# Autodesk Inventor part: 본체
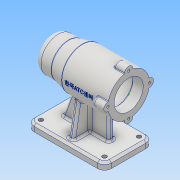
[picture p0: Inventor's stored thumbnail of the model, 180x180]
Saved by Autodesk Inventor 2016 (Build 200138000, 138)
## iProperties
Created: 2019-07
Part Number: 본체
Material: 알루미늄 6061
Document SubType Name: Modeling
Designer: 3sil_cad0123
Density: 2.7 g/cm^3
Appearance: 알루미늄 - 평지
Mass: 644.247 g
Surface Area: 655.732 cm^2
Volume: 238.61 cm^3
Author: 3sil_cad0123
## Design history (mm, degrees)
sketch "스케치1"
  geometry: 1 further point
sketch "스케치2"
  geometry: L1 (0, 0)-(0, 30); L2 (0, 30)-(-67, 30); L3 (-67, 30)-(-87, 25); L4 (-87, 25)-(-102, 25); L5 (-112, 15)-(-112, 0); L6 (-112, 0)-(0, 0); A1 r 10 centre (-102, 15) between (-102, 25) and (-112, 15); 1 further point
  constraints: 12 end point, 3 perpendicular, 2 point on circle, 2 point on line, 2 tangent, 1 centre point, 1 parallel, 1 vertical
  dimensions: "d0" = 112 distance between parallel lines of L1 L5; "d1" = 45 distance from line of L2.end L5; "d2" = 25 distance of L3.end point (-112, 25); "d3" = 60 diameter of L2 L6; "d4" = 50 diameter of L4 L6; "d5" = 10 radius of A1
revolve "회전1" sketch "스케치2" stored, may be unused: angle "d6" = 90 deg
sketch "스케치3"
  geometry: L1 (0, 0)-(-15, 0); L2 (-15, 0)-(-15, 21); L3 (-15, 21)-(0, 21); L4 (0, 21)-(0, 0); L5 (-15, 0)-(-69, 0); L6 (-69, 0)-(-69, 21); L7 (-66, 24)-(-18, 24); L8 (-15, 21)-(-15, 0); L9 (-69, 0)-(-81, 0); L10 (-81, 0)-(-81, 20.7); L11 (-80.7, 21)-(-69, 21); L12 (-69, 21)-(-69, 0); L13 (-81, 0)-(-99, 0); L14 (-99, 0)-(-99, 17.2); L15 (-98.7, 17.5)-(-81, 17.5); L16 (-81, 17.5)-(-81, 0); L17 (-99, 0)-(-103, 0); L18 (-103, 0)-(-103, 15.7); L19 (-102.7, 16)-(-99, 16); L20 (-99, 16)-(-99, 0); L21 (-103, 0)-(-106, 0); L22 (-106, 0)-(-106, 10.5); L23 (-106, 10.5)-(-103, 10.5); L24 (-103, 10.5)-(-103, 0); A1 r 0.3 centre (-80.7, 20.7) between (-80.7, 21) and (-81, 20.7); A2 r 0.3 centre (-98.7, 17.2) between (-98.7, 17.5) and (-99, 17.2); A3 r 0.3 centre (-102.7, 15.7) between (-102.7, 16) and (-103, 15.7); A4 r 3 centre (-66, 21) between (-66, 24) and (-69, 21); A5 r 3 centre (-18, 21) between (-15, 21) and (-18, 24); 5 further points
  constraints: 48 end point, 12 parallel, 10 point on circle, 10 point on line, 10 tangent, 6 horizontal, 6 perpendicular, 5 centre point, 3 equal radius
  dimensions: "d9" = 21 distance between parallel lines of L9 L11; "d10" = 17.5 distance between parallel lines of L13 L15; "d11" = 16 distance between parallel lines of L17 L19; "d12" = 10.5 distance between parallel lines of L21 L23; "d13" = 15 distance of L2.end L3.end; "d14" = 24 distance between parallel lines of L5 L7; "d15" = 21 distance between parallel lines of L1 L3; "d16" = 54 distance of point (-69, 24) point (-15, 24); "d17" = 12 distance of point (-81, 21) L11.end; "d18" = 18 distance of point (-99, 17.5) L15.end; "d19" = 4 distance of point (-103, 16) L19.end; "d20" = 3 distance of L22.end L23.end; "d21" = 0.3 radius of A1; "d22" = 3 radius of A4
revolve "회전2" sketch "스케치3" stored, may be unused: angle "d23" = 90 deg
sketch "스케치4"
  geometry: C1 r 21 at (0, 0) reference; C2 r 6 at (0, 30); C3 r 6 at (-30, 0); C4 r 6 at (0, -30); C5 r 6 at (30, 0); 1 further point
  constraints: 4 centre point, 1 vertical alignment, 10 other
  dimensions: "d26" = 360 deg dimension on C1.centre C2.centre (derived)
extrude "돌출1" join sketch "스케치4" distance "d28" = 16; taper "d29" = 0 deg
sketch "스케치5"
  geometry: A1 r 6 centre (30, 30) between (35.97, 29.4) and (24.03, 29.4) reference; A2 r 6 centre (0, 0) between (0.6, 5.97) and (0.6, -5.97) reference; A3 r 6 centre (30, -30) between (24.03, -29.4) and (35.97, -29.4) reference; A4 r 6 centre (60, 0) between (59.4, -5.97) and (59.4, 5.97) reference
hole "구멍1" sketch "스케치5" at (60, 0), (30, -30), (0, 0), (30, 30) diameter "d30" = 3.242; stored, may be unused: countersink angle "d34" = 90 deg, drill point angle "d36" = 118 deg; dims "d31" = 8, "d32" = 4, "d33" = 2, "d35" = 11
fillet "모깎기1" dims "d37" = 3
fillet "모깎기2" dims "d38" = 1
node "작업 평면1"
sketch "스케치6"
  geometry: L1 (0, -35)-(112, -35); L2 (112, -35)-(112, 35); L3 (112, 35)-(0, 35); L4 (0, 35)-(0, -35); 2 further points
  constraints: 8 end point, 2 parallel, 1 coincident, 1 horizontal, 1 midpoint, 1 perpendicular
  dimensions: "d40" = 112 distance of L2.end L3.end; "d41" = 70 distance of L1.end L2.end
extrude "돌출2" join sketch "스케치6" distance "d42" = 10; taper "d43" = 0 deg
fillet "모깎기3" dims "d44" = 10
sketch "스케치7"
  geometry: A1 r 10 centre (102, -25) between (102, -35) and (112, -25) reference; A2 r 10 centre (102, 25) between (112, 25) and (102, 35) reference; A3 r 10 centre (10, 25) between (10, 35) and (0, 25) reference; A4 r 10 centre (10, -25) between (0, -25) and (10, -35) reference; 1 further point
hole "구멍2" sketch "스케치7" at (10, 25), (10, -25), (102, -25), (102, 25) diameter "d45" = 6; stored, may be unused: countersink angle "d49" = 90 deg, drill point angle "d51" = 118 deg; dims "d46" = 8, "d47" = 4, "d48" = 2, "d50" = 11
node "작업 평면2"
sketch "스케치8"
  geometry: L1 (0, 6.771)-(0, 29.226) reference; 2 further points
  constraints: 1 horizontal alignment, 1 other
  dimensions: "d53" = 42 distance from line of L1 point (-42, 0)
feature "엠보싱1" sketch "스케치8" dims "d0" = 112, "d1" = 45, "d2" = 25, "d3" = 60, "d4" = 50, "d5" = 10, "d54" = 0.5, "d55" = 0
node "작업 평면3"
sketch "스케치10"
  geometry: L1 (-35, -70)-(-25, -70) reference; L2 (-28, -70)-(-19.207, -20.133); L3 (19.206, -20.126)-(28, -70); L4 (25, -70)-(35, -70) reference; L5 (-28, -70)-(28, -70); L6 (-35, -80)-(-35, -70) reference; L7 (35, -70)-(35, -80) reference; L8 (-19.207, -20.133)-(-5.193, -26.929); L9 (-5.193, -26.929)-(5.853, -26.929); L10 (5.853, -26.929)-(19.206, -20.126); 1 further point
  constraints: 12 end point, 2 point on line, 1 collinear, 1 horizontal
  dimensions: "d61" = 7 distance from line of L2.start L6; "d62" = 7 distance from line of L3.end L7; "d63" = 100 deg angle of L3 L4; "d64" = 100 deg angle of L1 L2
extrude "돌출3" join sketch "스케치10" stored distance "d65" = 8; taper "d66" = 0 deg
sketch "스케치11"
  geometry: L1 (-10, -70)-(-102, -70) reference; L2 (-92, -70)-(-83.173, -45.749); L3 (-112, -80)-(-112, -70) reference; 1 further point
  constraints: 2 end point, 1 point on line
  dimensions: "d67" = 20 distance from line of L3 L2.start; "d68" = 110 deg angle of L1 L2
feature "리브1" sketch "스케치11" dims "d69" = 1, "d70" = 8, "d71" = 0, "d72" = 0, "d73" = 1, "d74" = 1
sketch "스케치13"
  geometry: L1 (0, 25)-(0, -25) reference; L2 (52, -28)-(52, 28) reference; L3 (25, -4)-(52, -4); L4 (52, -4)-(52, 4); L5 (52, 4)-(25, 4); L6 (25, 4)-(25, -4); L7 (25, -4)-(52, 4); L8 (52, -4)-(25, 4); 4 further points
  constraints: 12 end point, 4 midpoint, 2 parallel, 1 horizontal, 1 horizontal alignment, 1 perpendicular, 1 point on line
  dimensions: "d75" = 25 distance between parallel lines of L6 L1; "d76" = 8 distance of L5.end L3.start
extrude "돌출4" join sketch "스케치13" stored distance "d77" = 8; taper "d78" = 0 deg
fillet "모깎기4" dims "d79" = 3
fillet "모깎기5" dims "d80" = 3
chamfer "모따기1" distance "d82" = 3; stored, may be unused: second distance "d83" = 2, angle "d84" = 45 deg
fillet "모깎기7" dims "d85" = 3
fillet "모깎기8" dims "d86" = 3
node "솔리드1"
other parameters: "d52" = 44.75, "d60" = 56
